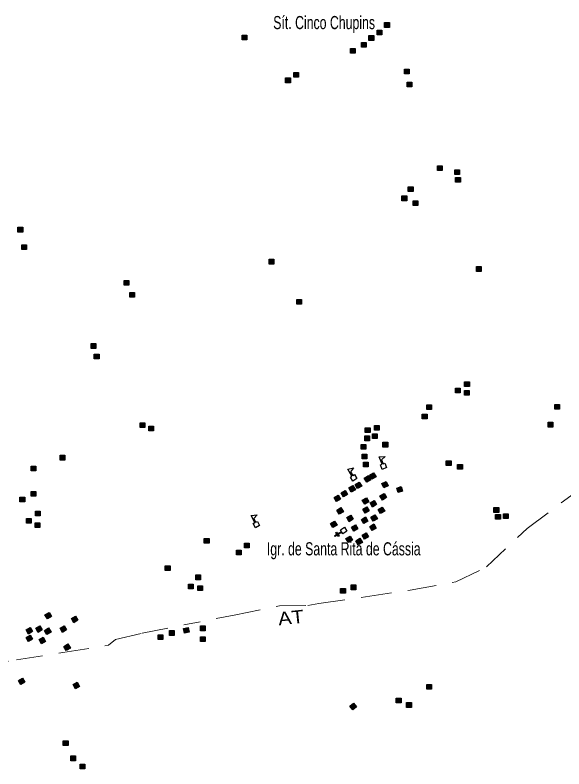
# Model space of a CAD drawing. Extents: x 220.8 to 246.7, y 7287.6 to 7315.8.
# Drawn here: x 239.906 to 243.25, y 7306.556 to 7311.146 of the extents above; entities that cross this region are included whole.
import ezdxf
from ezdxf.enums import TextEntityAlignment as Align

# ---------------------------------------------------------------- set-up
doc = ezdxf.new("R2010")
doc.units = 0
doc.header["$LTSCALE"] = 0.032
doc.linetypes.add('DOT_DASHED', pattern=[7.7, 5, -1.2, 0.3, -1.2])
for name, color, linetype, lineweight in [('2', 7, 'Continuous', 25), ('4', 7, 'Continuous', 25), ('56', 7, 'DOT_DASHED', 13), ('6', 7, 'Continuous', 25)]:
    doc.layers.add(name, color=color, linetype=linetype, lineweight=lineweight)
doc.layers.add('61', color=7, linetype='Continuous')

msp = doc.modelspace()

# ---------------------------------------------------------------- hatches: boundary and pattern name
at = {"layer": '2'}
for points in [[(242.1575, 7311.1006), (242.1865, 7311.1006), (242.1865, 7311.0716), (242.1575, 7311.0716)], [(242.1117, 7311.0548), (242.1407, 7311.0548), (242.1407, 7311.0258), (242.1117, 7311.0258)], [(241.2898, 7311.0244), (241.3188, 7311.0244), (241.3188, 7310.9954), (241.2898, 7310.9954)], [(242.0618, 7311.0215), (242.0908, 7311.0215), (242.0908, 7310.9925), (242.0618, 7310.9925)], [(242.016, 7310.9799), (242.045, 7310.9799), (242.045, 7310.9509), (242.016, 7310.9509)], [(241.9494, 7310.9425), (241.9784, 7310.9425), (241.9784, 7310.9135), (241.9494, 7310.9135)], [(241.604, 7310.7968), (241.633, 7310.7968), (241.633, 7310.7678), (241.604, 7310.7678)], [(242.2781, 7310.8176), (242.3071, 7310.8176), (242.3071, 7310.7886), (242.2781, 7310.7886)], [(241.5541, 7310.7635), (241.5831, 7310.7635), (241.5831, 7310.7345), (241.5541, 7310.7345)], [(242.2948, 7310.7385), (242.3238, 7310.7385), (242.3238, 7310.7095), (242.2948, 7310.7095)], [(242.4788, 7310.2282), (242.5078, 7310.2282), (242.5078, 7310.1992), (242.4788, 7310.1992)], [(242.5855, 7310.2047), (242.6145, 7310.2047), (242.6145, 7310.1757), (242.5855, 7310.1757)], [(242.5898, 7310.1578), (242.6188, 7310.1578), (242.6188, 7310.1288), (242.5898, 7310.1288)], [(242.3017, 7310.1002), (242.3307, 7310.1002), (242.3307, 7310.0712), (242.3017, 7310.0712)], [(242.2633, 7310.0447), (242.2923, 7310.0447), (242.2923, 7310.0157), (242.2633, 7310.0157)], [(242.3316, 7310.0148), (242.3606, 7310.0148), (242.3606, 7309.9858), (242.3316, 7309.9858)], [(239.9239, 7309.854), (239.9529, 7309.854), (239.9529, 7309.825), (239.9239, 7309.825)], [(239.947, 7309.7475), (239.976, 7309.7475), (239.976, 7309.7185), (239.947, 7309.7185)], [(241.4542, 7309.6592), (241.4832, 7309.6592), (241.4832, 7309.6302), (241.4542, 7309.6302)], [(242.7165, 7309.6145), (242.7455, 7309.6145), (242.7455, 7309.5855), (242.7165, 7309.5855)], [(240.5698, 7309.5297), (240.5988, 7309.5297), (240.5988, 7309.5007), (240.5698, 7309.5007)], [(240.6045, 7309.4577), (240.6335, 7309.4577), (240.6335, 7309.4287), (240.6045, 7309.4287)], [(241.6227, 7309.4145), (241.6517, 7309.4145), (241.6517, 7309.3855), (241.6227, 7309.3855)], [(240.37, 7309.1459), (240.399, 7309.1459), (240.399, 7309.1169), (240.37, 7309.1169)], [(240.3886, 7309.082), (240.4176, 7309.082), (240.4176, 7309.053), (240.3886, 7309.053)], [(242.6449, 7308.914), (242.6739, 7308.914), (242.6739, 7308.885), (242.6449, 7308.885)], [(242.5884, 7308.8748), (242.6174, 7308.8748), (242.6174, 7308.8458), (242.5884, 7308.8458)], [(242.6438, 7308.8609), (242.6728, 7308.8609), (242.6728, 7308.8319), (242.6438, 7308.8319)], [(242.4148, 7308.774), (242.4438, 7308.774), (242.4438, 7308.745), (242.4148, 7308.745)], [(243.1942, 7308.7759), (243.2232, 7308.7759), (243.2232, 7308.7469), (243.1942, 7308.7469)], [(242.3872, 7308.716), (242.4162, 7308.716), (242.4162, 7308.687), (242.3872, 7308.687)], [(240.6672, 7308.6643), (240.6962, 7308.6643), (240.6962, 7308.6353), (240.6672, 7308.6353)], [(243.153, 7308.667), (243.182, 7308.667), (243.182, 7308.638), (243.153, 7308.638)], [(240.7205, 7308.6428), (240.7495, 7308.6428), (240.7495, 7308.6138), (240.7205, 7308.6138)], [(242.0397, 7308.6333), (242.0687, 7308.6333), (242.0687, 7308.6043), (242.0397, 7308.6043)], [(242.0948, 7308.6471), (242.1238, 7308.6471), (242.1238, 7308.6181), (242.0948, 7308.6181)], [(242.0369, 7308.5837), (242.0659, 7308.5837), (242.0659, 7308.5547), (242.0369, 7308.5547)], [(242.0838, 7308.5974), (242.1128, 7308.5974), (242.1128, 7308.5684), (242.0838, 7308.5684)], [(242.0149, 7308.5312), (242.0439, 7308.5312), (242.0439, 7308.5022), (242.0149, 7308.5022)], [(242.1472, 7308.545), (242.1762, 7308.545), (242.1762, 7308.516), (242.1472, 7308.516)], [(240.1808, 7308.466), (240.2098, 7308.466), (240.2098, 7308.437), (240.1808, 7308.437)], [(242.0204, 7308.4733), (242.0494, 7308.4733), (242.0494, 7308.4443), (242.0204, 7308.4443)], [(240.0044, 7308.4002), (240.0334, 7308.4002), (240.0334, 7308.3712), (240.0044, 7308.3712)], [(242.0286, 7308.4237), (242.0576, 7308.4237), (242.0576, 7308.3947), (242.0286, 7308.3947)], [(242.5334, 7308.4319), (242.5624, 7308.4319), (242.5624, 7308.4029), (242.5334, 7308.4029)], [(242.6023, 7308.4099), (242.6313, 7308.4099), (242.6313, 7308.3809), (242.6023, 7308.3809)], [(242.0658, 7308.3446), (242.0907, 7308.3593), (242.1055, 7308.3344), (242.0805, 7308.3196)], [(241.9784, 7308.2881), (242.0033, 7308.3028), (242.0181, 7308.2779), (241.9931, 7308.2631)], [(242.0336, 7308.3271), (242.0585, 7308.3418), (242.0733, 7308.3169), (242.0483, 7308.3021)], [(242.1406, 7308.2942), (242.1672, 7308.3056), (242.1787, 7308.279), (242.1519, 7308.2675)], [(241.8924, 7308.2371), (241.9173, 7308.2518), (241.9321, 7308.2269), (241.9071, 7308.2121)], [(241.9394, 7308.2666), (241.9643, 7308.2813), (241.9791, 7308.2564), (241.9541, 7308.2416)], [(242.231, 7308.2663), (242.2586, 7308.275), (242.2673, 7308.2474), (242.2396, 7308.2386)], [(239.9359, 7308.2106), (239.9649, 7308.2106), (239.9649, 7308.1816), (239.9359, 7308.1816)], [(240.0044, 7308.2449), (240.0334, 7308.2449), (240.0334, 7308.2159), (240.0044, 7308.2159)], [(241.8493, 7308.2088), (241.8742, 7308.2235), (241.889, 7308.1986), (241.864, 7308.1838)], [(242.0214, 7308.1927), (242.0463, 7308.2074), (242.0611, 7308.1825), (242.0361, 7308.1677)], [(242.129, 7308.2183), (242.1539, 7308.233), (242.1687, 7308.2081), (242.1437, 7308.1933)], [(242.0693, 7308.1758), (242.0942, 7308.1905), (242.109, 7308.1656), (242.084, 7308.1508)], [(240.0307, 7308.1264), (240.0597, 7308.1264), (240.0597, 7308.0974), (240.0307, 7308.0974)], [(241.8668, 7308.1322), (241.8917, 7308.1469), (241.9065, 7308.122), (241.8815, 7308.1072)], [(242.0246, 7308.1379), (242.0495, 7308.1526), (242.0643, 7308.1277), (242.0393, 7308.1129)], [(242.1184, 7308.1356), (242.1433, 7308.1503), (242.1581, 7308.1254), (242.1331, 7308.1106)], [(242.8236, 7308.147), (242.8526, 7308.147), (242.8526, 7308.118), (242.8236, 7308.118)], [(239.9754, 7308.0816), (240.0044, 7308.0816), (240.0044, 7308.0526), (239.9754, 7308.0526)], [(241.9264, 7308.0865), (241.9513, 7308.1012), (241.9661, 7308.0763), (241.9411, 7308.0615)], [(242.0157, 7308.0754), (242.0406, 7308.0901), (242.0554, 7308.0652), (242.0304, 7308.0504)], [(242.0737, 7308.0887), (242.0986, 7308.1034), (242.1134, 7308.0785), (242.0884, 7308.0637)], [(242.8335, 7308.1056), (242.8625, 7308.1056), (242.8625, 7308.0766), (242.8335, 7308.0766)], [(242.8816, 7308.1089), (242.9106, 7308.1089), (242.9106, 7308.0799), (242.8816, 7308.0799)], [(240.0281, 7308.0553), (240.0571, 7308.0553), (240.0571, 7308.0263), (240.0281, 7308.0263)], [(241.8281, 7308.0508), (241.853, 7308.0655), (241.8678, 7308.0406), (241.8428, 7308.0258)], [(241.9554, 7308.0285), (241.9803, 7308.0432), (241.9951, 7308.0183), (241.9701, 7308.0035)], [(242.067, 7308.0329), (242.0919, 7308.0476), (242.1067, 7308.0227), (242.0817, 7308.0079)], [(242.0201, 7307.9793), (242.045, 7307.994), (242.0598, 7307.9691), (242.0348, 7307.9543)], [(241.0587, 7307.9591), (241.0877, 7307.9591), (241.0877, 7307.9301), (241.0587, 7307.9301)], [(241.3039, 7307.9315), (241.3329, 7307.9315), (241.3329, 7307.9025), (241.3039, 7307.9025)], [(241.9219, 7307.9592), (241.9468, 7307.9739), (241.9616, 7307.949), (241.9366, 7307.9342)], [(241.9822, 7307.9458), (242.0071, 7307.9605), (242.0219, 7307.9356), (241.9969, 7307.9208)], [(241.2549, 7307.8886), (241.2839, 7307.8886), (241.2839, 7307.8596), (241.2549, 7307.8596)], [(240.8215, 7307.7936), (240.8505, 7307.7936), (240.8505, 7307.7646), (240.8215, 7307.7646)], [(241.0066, 7307.7371), (241.0356, 7307.7371), (241.0356, 7307.7081), (241.0066, 7307.7081)], [(240.9626, 7307.6807), (240.9916, 7307.6807), (240.9916, 7307.6517), (240.9626, 7307.6517)], [(241.0191, 7307.6713), (241.0481, 7307.6713), (241.0481, 7307.6423), (241.0191, 7307.6423)], [(241.8894, 7307.6548), (241.9184, 7307.6548), (241.9184, 7307.6258), (241.8894, 7307.6258)], [(241.953, 7307.6765), (241.982, 7307.6765), (241.982, 7307.6475), (241.953, 7307.6475)], [(240.0881, 7307.4942), (240.113, 7307.5089), (240.1278, 7307.484), (240.1028, 7307.4692)], [(240.2495, 7307.4712), (240.2744, 7307.4859), (240.2892, 7307.461), (240.2642, 7307.4462)], [(240.0318, 7307.4123), (240.0567, 7307.427), (240.0715, 7307.4021), (240.0465, 7307.3873)], [(240.1803, 7307.4123), (240.2052, 7307.427), (240.22, 7307.4021), (240.195, 7307.3873)], [(241.0348, 7307.4266), (241.0638, 7307.4266), (241.0638, 7307.3976), (241.0348, 7307.3976)], [(239.9729, 7307.402), (239.9978, 7307.4167), (240.0126, 7307.3918), (239.9876, 7307.377)], [(240.0856, 7307.3995), (240.1105, 7307.4142), (240.1253, 7307.3893), (240.1003, 7307.3745)], [(240.8466, 7307.3984), (240.8756, 7307.3984), (240.8756, 7307.3694), (240.8466, 7307.3694)], [(240.9331, 7307.4112), (240.9616, 7307.4166), (240.967, 7307.3881), (240.9385, 7307.3827)], [(239.9729, 7307.3559), (239.9978, 7307.3706), (240.0126, 7307.3457), (239.9876, 7307.3309)], [(240.0523, 7307.3431), (240.0772, 7307.3578), (240.092, 7307.3329), (240.067, 7307.3181)], [(240.7776, 7307.3733), (240.8066, 7307.3733), (240.8066, 7307.3443), (240.7776, 7307.3443)], [(241.0348, 7307.3607), (241.0638, 7307.3607), (241.0638, 7307.3317), (241.0348, 7307.3317)], [(240.2034, 7307.3022), (240.2283, 7307.3169), (240.2431, 7307.292), (240.2181, 7307.2772)], [(239.9268, 7307.0947), (239.9517, 7307.1094), (239.9665, 7307.0845), (239.9415, 7307.0697)], [(240.2597, 7307.0691), (240.2846, 7307.0838), (240.2994, 7307.0589), (240.2744, 7307.0441)], [(242.4149, 7307.0708), (242.4439, 7307.0708), (242.4439, 7307.0418), (242.4149, 7307.0418)], [(242.2288, 7306.9867), (242.2578, 7306.9867), (242.2578, 7306.9577), (242.2288, 7306.9577)], [(241.9457, 7306.9383), (241.9678, 7306.9571), (241.9866, 7306.935), (241.9645, 7306.9162)], [(242.2917, 7306.96), (242.3207, 7306.96), (242.3207, 7306.931), (242.2917, 7306.931)], [(240.2, 7306.7274), (240.229, 7306.7274), (240.229, 7306.6984), (240.2, 7306.6984)], [(240.2449, 7306.635), (240.2739, 7306.635), (240.2739, 7306.606), (240.2449, 7306.606)], [(240.3024, 7306.585), (240.3314, 7306.585), (240.3314, 7306.556), (240.3024, 7306.556)]]:
    msp.add_hatch(color=256, dxfattribs=at).paths.add_polyline_path(points)

# ---------------------------------------------------------------- linework, layer by layer
for points in [[(242.1575, 7311.1006), (242.1865, 7311.1006), (242.1865, 7311.0716), (242.1575, 7311.0716)], [(242.1117, 7311.0548), (242.1407, 7311.0548), (242.1407, 7311.0258), (242.1117, 7311.0258)], [(241.2898, 7311.0244), (241.3188, 7311.0244), (241.3188, 7310.9954), (241.2898, 7310.9954)], [(242.0618, 7311.0215), (242.0908, 7311.0215), (242.0908, 7310.9925), (242.0618, 7310.9925)], [(242.016, 7310.9799), (242.045, 7310.9799), (242.045, 7310.9509), (242.016, 7310.9509)], [(241.9494, 7310.9425), (241.9784, 7310.9425), (241.9784, 7310.9135), (241.9494, 7310.9135)], [(241.604, 7310.7968), (241.633, 7310.7968), (241.633, 7310.7678), (241.604, 7310.7678)], [(242.2781, 7310.8176), (242.3071, 7310.8176), (242.3071, 7310.7886), (242.2781, 7310.7886)], [(241.5541, 7310.7635), (241.5831, 7310.7635), (241.5831, 7310.7345), (241.5541, 7310.7345)], [(242.2948, 7310.7385), (242.3238, 7310.7385), (242.3238, 7310.7095), (242.2948, 7310.7095)], [(242.4788, 7310.2282), (242.5078, 7310.2282), (242.5078, 7310.1992), (242.4788, 7310.1992)], [(242.5855, 7310.2047), (242.6145, 7310.2047), (242.6145, 7310.1757), (242.5855, 7310.1757)], [(242.5898, 7310.1578), (242.6188, 7310.1578), (242.6188, 7310.1288), (242.5898, 7310.1288)], [(242.3017, 7310.1002), (242.3307, 7310.1002), (242.3307, 7310.0712), (242.3017, 7310.0712)], [(242.2633, 7310.0447), (242.2923, 7310.0447), (242.2923, 7310.0157), (242.2633, 7310.0157)], [(242.3316, 7310.0148), (242.3606, 7310.0148), (242.3606, 7309.9858), (242.3316, 7309.9858)], [(239.9239, 7309.854), (239.9529, 7309.854), (239.9529, 7309.825), (239.9239, 7309.825)], [(239.947, 7309.7475), (239.976, 7309.7475), (239.976, 7309.7185), (239.947, 7309.7185)], [(241.4542, 7309.6592), (241.4832, 7309.6592), (241.4832, 7309.6302), (241.4542, 7309.6302)], [(242.7165, 7309.6145), (242.7455, 7309.6145), (242.7455, 7309.5855), (242.7165, 7309.5855)], [(240.5698, 7309.5297), (240.5988, 7309.5297), (240.5988, 7309.5007), (240.5698, 7309.5007)], [(240.6045, 7309.4577), (240.6335, 7309.4577), (240.6335, 7309.4287), (240.6045, 7309.4287)], [(241.6227, 7309.4145), (241.6517, 7309.4145), (241.6517, 7309.3855), (241.6227, 7309.3855)], [(240.37, 7309.1459), (240.399, 7309.1459), (240.399, 7309.1169), (240.37, 7309.1169)], [(240.3886, 7309.082), (240.4176, 7309.082), (240.4176, 7309.053), (240.3886, 7309.053)], [(242.6449, 7308.914), (242.6739, 7308.914), (242.6739, 7308.885), (242.6449, 7308.885)], [(242.5884, 7308.8748), (242.6174, 7308.8748), (242.6174, 7308.8458), (242.5884, 7308.8458)], [(242.6438, 7308.8609), (242.6728, 7308.8609), (242.6728, 7308.8319), (242.6438, 7308.8319)], [(242.4148, 7308.774), (242.4438, 7308.774), (242.4438, 7308.745), (242.4148, 7308.745)], [(243.1942, 7308.7759), (243.2232, 7308.7759), (243.2232, 7308.7469), (243.1942, 7308.7469)], [(242.3872, 7308.716), (242.4162, 7308.716), (242.4162, 7308.687), (242.3872, 7308.687)], [(240.6672, 7308.6643), (240.6962, 7308.6643), (240.6962, 7308.6353), (240.6672, 7308.6353)], [(243.153, 7308.667), (243.182, 7308.667), (243.182, 7308.638), (243.153, 7308.638)], [(240.7205, 7308.6428), (240.7495, 7308.6428), (240.7495, 7308.6138), (240.7205, 7308.6138)], [(242.0397, 7308.6333), (242.0687, 7308.6333), (242.0687, 7308.6043), (242.0397, 7308.6043)], [(242.0948, 7308.6471), (242.1238, 7308.6471), (242.1238, 7308.6181), (242.0948, 7308.6181)], [(242.0369, 7308.5837), (242.0659, 7308.5837), (242.0659, 7308.5547), (242.0369, 7308.5547)], [(242.0838, 7308.5974), (242.1128, 7308.5974), (242.1128, 7308.5684), (242.0838, 7308.5684)], [(242.0149, 7308.5312), (242.0439, 7308.5312), (242.0439, 7308.5022), (242.0149, 7308.5022)], [(242.1472, 7308.545), (242.1762, 7308.545), (242.1762, 7308.516), (242.1472, 7308.516)], [(240.1808, 7308.466), (240.2098, 7308.466), (240.2098, 7308.437), (240.1808, 7308.437)], [(242.0204, 7308.4733), (242.0494, 7308.4733), (242.0494, 7308.4443), (242.0204, 7308.4443)], [(240.0044, 7308.4002), (240.0334, 7308.4002), (240.0334, 7308.3712), (240.0044, 7308.3712)], [(242.0286, 7308.4237), (242.0576, 7308.4237), (242.0576, 7308.3947), (242.0286, 7308.3947)], [(242.5334, 7308.4319), (242.5624, 7308.4319), (242.5624, 7308.4029), (242.5334, 7308.4029)], [(242.6023, 7308.4099), (242.6313, 7308.4099), (242.6313, 7308.3809), (242.6023, 7308.3809)], [(242.0658, 7308.3446), (242.0907, 7308.3593), (242.1055, 7308.3344), (242.0805, 7308.3196)], [(241.9784, 7308.2881), (242.0033, 7308.3028), (242.0181, 7308.2779), (241.9931, 7308.2631)], [(242.0336, 7308.3271), (242.0585, 7308.3418), (242.0733, 7308.3169), (242.0483, 7308.3021)], [(242.1406, 7308.2942), (242.1672, 7308.3056), (242.1787, 7308.279), (242.1519, 7308.2675)], [(241.8924, 7308.2371), (241.9173, 7308.2518), (241.9321, 7308.2269), (241.9071, 7308.2121)], [(241.9394, 7308.2666), (241.9643, 7308.2813), (241.9791, 7308.2564), (241.9541, 7308.2416)], [(242.231, 7308.2663), (242.2586, 7308.275), (242.2673, 7308.2474), (242.2396, 7308.2386)], [(239.9359, 7308.2106), (239.9649, 7308.2106), (239.9649, 7308.1816), (239.9359, 7308.1816)], [(240.0044, 7308.2449), (240.0334, 7308.2449), (240.0334, 7308.2159), (240.0044, 7308.2159)], [(241.8493, 7308.2088), (241.8742, 7308.2235), (241.889, 7308.1986), (241.864, 7308.1838)], [(242.0214, 7308.1927), (242.0463, 7308.2074), (242.0611, 7308.1825), (242.0361, 7308.1677)], [(242.129, 7308.2183), (242.1539, 7308.233), (242.1687, 7308.2081), (242.1437, 7308.1933)], [(242.0693, 7308.1758), (242.0942, 7308.1905), (242.109, 7308.1656), (242.084, 7308.1508)], [(240.0307, 7308.1264), (240.0597, 7308.1264), (240.0597, 7308.0974), (240.0307, 7308.0974)], [(241.8668, 7308.1322), (241.8917, 7308.1469), (241.9065, 7308.122), (241.8815, 7308.1072)], [(242.0246, 7308.1379), (242.0495, 7308.1526), (242.0643, 7308.1277), (242.0393, 7308.1129)], [(242.1184, 7308.1356), (242.1433, 7308.1503), (242.1581, 7308.1254), (242.1331, 7308.1106)], [(242.8236, 7308.147), (242.8526, 7308.147), (242.8526, 7308.118), (242.8236, 7308.118)], [(239.9754, 7308.0816), (240.0044, 7308.0816), (240.0044, 7308.0526), (239.9754, 7308.0526)], [(241.9264, 7308.0865), (241.9513, 7308.1012), (241.9661, 7308.0763), (241.9411, 7308.0615)], [(242.0157, 7308.0754), (242.0406, 7308.0901), (242.0554, 7308.0652), (242.0304, 7308.0504)], [(242.0737, 7308.0887), (242.0986, 7308.1034), (242.1134, 7308.0785), (242.0884, 7308.0637)], [(242.8335, 7308.1056), (242.8625, 7308.1056), (242.8625, 7308.0766), (242.8335, 7308.0766)], [(242.8816, 7308.1089), (242.9106, 7308.1089), (242.9106, 7308.0799), (242.8816, 7308.0799)], [(240.0281, 7308.0553), (240.0571, 7308.0553), (240.0571, 7308.0263), (240.0281, 7308.0263)], [(241.8281, 7308.0508), (241.853, 7308.0655), (241.8678, 7308.0406), (241.8428, 7308.0258)], [(241.9554, 7308.0285), (241.9803, 7308.0432), (241.9951, 7308.0183), (241.9701, 7308.0035)], [(242.067, 7308.0329), (242.0919, 7308.0476), (242.1067, 7308.0227), (242.0817, 7308.0079)], [(242.0201, 7307.9793), (242.045, 7307.994), (242.0598, 7307.9691), (242.0348, 7307.9543)], [(241.0587, 7307.9591), (241.0877, 7307.9591), (241.0877, 7307.9301), (241.0587, 7307.9301)], [(241.3039, 7307.9315), (241.3329, 7307.9315), (241.3329, 7307.9025), (241.3039, 7307.9025)], [(241.9219, 7307.9592), (241.9468, 7307.9739), (241.9616, 7307.949), (241.9366, 7307.9342)], [(241.9822, 7307.9458), (242.0071, 7307.9605), (242.0219, 7307.9356), (241.9969, 7307.9208)], [(241.2549, 7307.8886), (241.2839, 7307.8886), (241.2839, 7307.8596), (241.2549, 7307.8596)], [(240.8215, 7307.7936), (240.8505, 7307.7936), (240.8505, 7307.7646), (240.8215, 7307.7646)], [(241.0066, 7307.7371), (241.0356, 7307.7371), (241.0356, 7307.7081), (241.0066, 7307.7081)], [(240.9626, 7307.6807), (240.9916, 7307.6807), (240.9916, 7307.6517), (240.9626, 7307.6517)], [(241.0191, 7307.6713), (241.0481, 7307.6713), (241.0481, 7307.6423), (241.0191, 7307.6423)], [(241.8894, 7307.6548), (241.9184, 7307.6548), (241.9184, 7307.6258), (241.8894, 7307.6258)], [(241.953, 7307.6765), (241.982, 7307.6765), (241.982, 7307.6475), (241.953, 7307.6475)], [(240.0881, 7307.4942), (240.113, 7307.5089), (240.1278, 7307.484), (240.1028, 7307.4692)], [(240.2495, 7307.4712), (240.2744, 7307.4859), (240.2892, 7307.461), (240.2642, 7307.4462)], [(240.0318, 7307.4123), (240.0567, 7307.427), (240.0715, 7307.4021), (240.0465, 7307.3873)], [(240.1803, 7307.4123), (240.2052, 7307.427), (240.22, 7307.4021), (240.195, 7307.3873)], [(241.0348, 7307.4266), (241.0638, 7307.4266), (241.0638, 7307.3976), (241.0348, 7307.3976)], [(239.9729, 7307.402), (239.9978, 7307.4167), (240.0126, 7307.3918), (239.9876, 7307.377)], [(240.0856, 7307.3995), (240.1105, 7307.4142), (240.1253, 7307.3893), (240.1003, 7307.3745)], [(240.8466, 7307.3984), (240.8756, 7307.3984), (240.8756, 7307.3694), (240.8466, 7307.3694)], [(240.9331, 7307.4112), (240.9616, 7307.4166), (240.967, 7307.3881), (240.9385, 7307.3827)], [(239.9729, 7307.3559), (239.9978, 7307.3706), (240.0126, 7307.3457), (239.9876, 7307.3309)], [(240.0523, 7307.3431), (240.0772, 7307.3578), (240.092, 7307.3329), (240.067, 7307.3181)], [(240.7776, 7307.3733), (240.8066, 7307.3733), (240.8066, 7307.3443), (240.7776, 7307.3443)], [(241.0348, 7307.3607), (241.0638, 7307.3607), (241.0638, 7307.3317), (241.0348, 7307.3317)], [(240.2034, 7307.3022), (240.2283, 7307.3169), (240.2431, 7307.292), (240.2181, 7307.2772)], [(239.9268, 7307.0947), (239.9517, 7307.1094), (239.9665, 7307.0845), (239.9415, 7307.0697)], [(240.2597, 7307.0691), (240.2846, 7307.0838), (240.2994, 7307.0589), (240.2744, 7307.0441)], [(242.4149, 7307.0708), (242.4439, 7307.0708), (242.4439, 7307.0418), (242.4149, 7307.0418)], [(242.2288, 7306.9867), (242.2578, 7306.9867), (242.2578, 7306.9577), (242.2288, 7306.9577)], [(241.9457, 7306.9383), (241.9678, 7306.9571), (241.9866, 7306.935), (241.9645, 7306.9162)], [(242.2917, 7306.96), (242.3207, 7306.96), (242.3207, 7306.931), (242.2917, 7306.931)], [(240.2, 7306.7274), (240.229, 7306.7274), (240.229, 7306.6984), (240.2, 7306.6984)], [(240.2449, 7306.635), (240.2739, 7306.635), (240.2739, 7306.606), (240.2449, 7306.606)], [(240.3024, 7306.585), (240.3314, 7306.585), (240.3314, 7306.556), (240.3024, 7306.556)]]:
    msp.add_lwpolyline(points, close=True, dxfattribs=at)
at = {"layer": '4'}
for points in [[(242.1431, 7308.4112), (242.1249, 7308.456), (242.1607, 7308.458), (242.1378, 7308.4372), (242.1476, 7308.413)], [(241.9587, 7308.3394), (241.9329, 7308.3803), (241.9678, 7308.3886), (241.949, 7308.3641), (241.9629, 7308.342)], [(242.1476, 7308.413), (242.1588, 7308.4176), (242.1697, 7308.3907), (242.1428, 7308.3798), (242.132, 7308.4067), (242.1431, 7308.4112)], [(241.9629, 7308.342), (241.9731, 7308.3484), (241.9886, 7308.3239), (241.964, 7308.3085), (241.9486, 7308.333), (241.9587, 7308.3394)], [(241.3675, 7308.0557), (241.3449, 7308.0984), (241.3803, 7308.104), (241.3597, 7308.081), (241.3718, 7308.0579)], [(241.3718, 7308.0579), (241.3825, 7308.0635), (241.3961, 7308.0379), (241.3703, 7308.0244), (241.3569, 7308.0501), (241.3675, 7308.0557)]]:
    msp.add_lwpolyline(points, dxfattribs=at)
at = {"layer": '56'}
msp.add_lwpolyline([(239.7076, 7307.1857), (239.9155, 7307.2208), (240.1965, 7307.2648), (240.4747, 7307.3088), (240.5186, 7307.3439), (240.6797, 7307.382), (241.2418, 7307.4932), (241.5171, 7307.5488), (241.6898, 7307.5518), (241.7572, 7307.5635), (242.0412, 7307.6045), (242.3135, 7307.6454), (242.5917, 7307.6952), (242.779, 7307.7859), (243.025, 7308.0201), (243.432, 7308.3246)], dxfattribs=at)
at = {"layer": '6'}
for points in [[(241.8941, 7308.002), (241.8877, 7308.0122), (241.9122, 7308.0276), (241.9277, 7308.0031), (241.9031, 7307.9876), (241.8967, 7307.9979)], [(241.8967, 7307.9979), (241.8737, 7307.9835), (241.8802, 7307.9732), (241.876, 7307.9706), (241.8696, 7307.9809), (241.8557, 7307.9721), (241.8531, 7307.9762), (241.867, 7307.9849), (241.8606, 7307.9952), (241.8647, 7307.9978), (241.8712, 7307.9875), (241.8941, 7308.002)]]:
    msp.add_lwpolyline(points, dxfattribs=at)

# ---------------------------------------------------------------- texts
at = {"layer": '61', "width": 0.7}
msp.add_text('Sít. Cinco Chupins', height=0.08, dxfattribs=at).set_placement((242.099, 7311.0607), align=Align.RIGHT)
msp.add_text('Igr. de Santa Rita de Cássia', height=0.08, dxfattribs=at).set_placement((241.4401, 7307.8563))
at = {"layer": '61', "width": 1.15}
msp.add_text('AT', height=0.08, rotation=5.839, dxfattribs=at).set_placement((241.591, 7307.4382), align=Align.CENTER)

doc.saveas('drawing.dxf')
